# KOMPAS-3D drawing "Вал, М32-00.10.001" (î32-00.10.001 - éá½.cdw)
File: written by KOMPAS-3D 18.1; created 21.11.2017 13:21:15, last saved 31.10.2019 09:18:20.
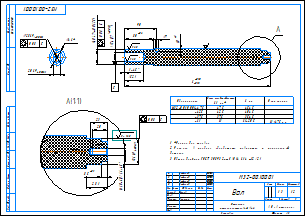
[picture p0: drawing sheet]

Sheet 1: A3, landscape

Document properties: Полное имя файла: D:\Magna\Магна Ins\Магна ins 32\Для Караби\М32-00.10.001 - Вал.cdw; Масса: 1.30054

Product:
- Part/product: Вал  | designation М32-00.10.001  | pos. 0
    Масса: 1.30054
    Раздел спецификации: Детали
    Форматы листов документа: A3
    source file: М32-00.10.001 - Вал.cdw

Title block, sheet 1: Наименование: Вал; designation: М32-00.10.001; Масса: 1,3; scale: 1:2; Количество листов документа: 1; organisation: АО «Астерион»; Форматы листов документа: A3; stored path: D:\Отработать\Магна 40\Чертежи\М40-00.10.001 - Вал.cdw; Разработал: Милов; Т. контр.: Лучихин

Views: Вид 1, Вид:1, Проекционный вид 2, Местный разрез 1, Выносной элемент 3, Выносной элемент А, Выносной элемент
Referenced files in D:\Отработать\Магна 40\3Д\: М40-00.10.001 - Вал.m3d
Referenced files in Z:\Магна\Магна Ins\Магна ins 32\: М32-00.10.001 - Вал.m3d
Referenced files in D:\Magna\Магна Ins\Магна ins 32\: М32-00.10.001 - Вал.m3d
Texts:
  Стержень
  стеклопластиковый  46
  js7( 0,0125)
  js7
  Ra 1,25
  Длина погружной части
  L1, мм*
  L, мм
  L1 475 мм
  Лифлянд
Dimensions and other numbers on the sheet: 28; 20; 46; 0,08; 80; 90; 10; 7; 52; 24; 1,25; 40; 1; -6Н/1,6х45; 23; 8,5; 28,1; 36; 475; 454,5; -425; -375; 425; 375; 404,5; 354,5; 5; 1:2; 1,3; 22.08.2019; 6; 30.10.2019; 3; 12.07.2019; 4; 31.07.2019

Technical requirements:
  *Размер для справок.
  Размеры в скобках обработать совместно с сопрягаемой
  деталью.
  Общие допуски ГОСТ 30893.2-тК (H14, h14,  t2/2).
